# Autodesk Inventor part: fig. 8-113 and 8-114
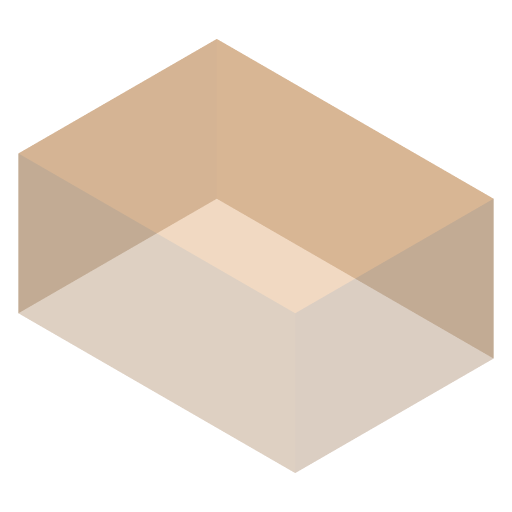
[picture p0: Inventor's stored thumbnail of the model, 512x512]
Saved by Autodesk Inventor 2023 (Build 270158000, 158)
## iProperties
Created: 2013-07
Part Number: fig. 8-113 and 8-114
Material: Generic
Document SubType Name: Modeling
Designer: CADCIM
Density: 1 g/cm^3
Appearance: Default
Author: CADCIM
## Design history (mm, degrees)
sketch "Sketch1"
  geometry: L1 (-10, 7.167)-(10, 7.167); L2 (10, 7.167)-(10, -7.167); L3 (10, -7.167)-(-10, -7.167); L4 (-10, -7.167)-(-10, 7.167); L5 (-10, 7.167)-(10, -7.167); L6 (10, 7.167)-(-10, -7.167); 1 further point
  constraints: 12 end point, 2 equal length, 2 midpoint, 1 horizontal, 1 parallel
  dimensions: "d0" = 20 distance of L2.end L3.end
extrude_surface "ExtrusionSrf1" sketch "Sketch1" dims "d1" = 10, "d2" = 0
patch "Boundary Patch1" dims "d3" = 5, "d4" = 0
body "Srf1"
body "Srf2"
